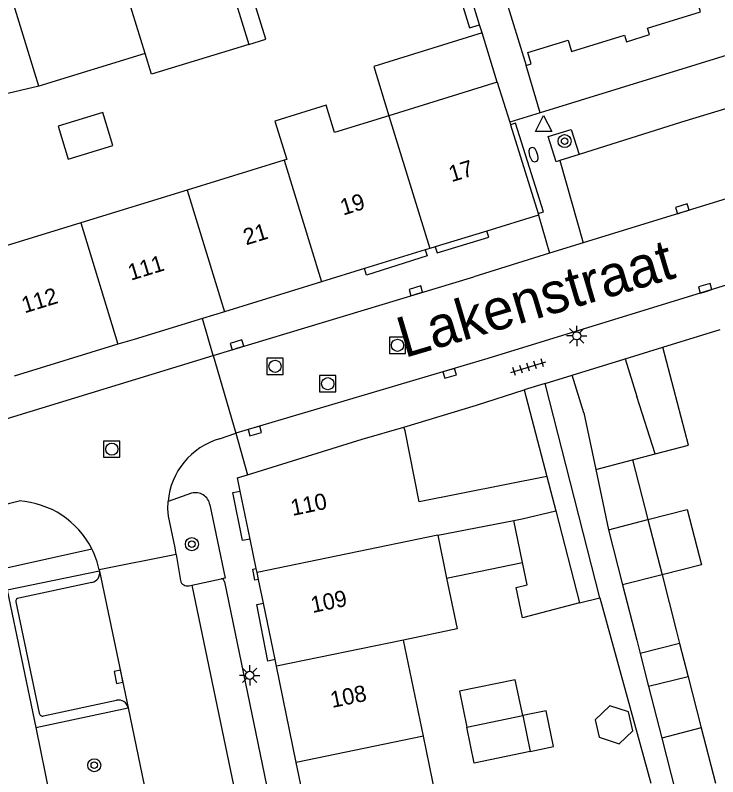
# Model space of a CAD drawing. Extents: x 132999 to 136000, y 398499 to 400501.
# Drawn here: x 133326.11 to 133369.25, y 398548.28 to 398595.04 of the extents above; entities that cross this region are included whole.
import ezdxf

# ---------------------------------------------------------------- set-up
doc = ezdxf.new("R2010")
doc.units = 0
for name, color, linetype in [('gg-afsc-erfafscheiding', 7, 'Continuous'), ('gg-afsc-muur', 7, 'Continuous'), ('gg-anno-huisnummerreeks BGT', 7, 'Continuous'), ('gg-anno-openbare ruimte label', 7, 'Continuous'), ('gg-bbg-bijgebouw', 7, 'Continuous'), ('gg-bbg-gedigitaliseerde bebouwing', 7, 'Continuous'), ('gg-bbg-gedigitaliseerde bijgebouw', 7, 'Continuous'), ('gg-bbg-hoofdgebouw', 7, 'Continuous'), ('gg-bbg-luifel en loopbrug', 7, 'Continuous'), ('gg-bbg-tussenscheiding', 7, 'Continuous'), ('gg-knt-verharding', 7, 'Continuous'), ('gg-knt-verharding nz', 7, 'Continuous'), ('gt-grn-groengrens', 7, 'Continuous'), ('gt-grn-weggrens', 7, 'Continuous'), ('gt-symb-boom', 7, 'Continuous'), ('gt-symb-brandkraan', 7, 'Continuous'), ('gt-symb-kolk', 7, 'Continuous'), ('gt-symb-lichtmast', 7, 'Continuous'), ('gt-symb-rioolschacht', 7, 'Continuous'), ('gt-symb-tegel verharding', 7, 'Continuous'), ('gt-symb-waterafsluiter', 7, 'Continuous')]:
    doc.layers.add(name, color=color, linetype=linetype)

# ---------------------------------------------------------------- blocks, each defined once
blk = doc.blocks.new('gt0-BR')
at = {"layer": 'gt-symb-brandkraan'}
for centre, radius, start, end in [((-0.244, 0), 0.206, 107.5669, 252.4331), ((0.599, -2.664), 3, 106.892, 107.5669), ((0, -0.691), 0.938, 73.108, 106.892), ((-0.599, -2.664), 3, 72.4331, 73.108), ((0.244, 0), 0.206, 287.567, 72.4331), ((0.599, 2.664), 3, 252.4331, 253.108), ((0, 0.691), 0.938, 253.108, 286.8921), ((-0.599, 2.664), 3, 286.8921, 287.567)]:
    blk.add_arc(centre, radius, start, end, dxfattribs=at)
blk = doc.blocks.new('gt0-WAFSL')
at = {"layer": 'gt-symb-waterafsluiter'}
for p, q in [((-0.5, -0.333), (0, 0.667)), ((0, 0.667), (0.5, -0.333)), ((0.5, -0.333), (-0.5, -0.333))]:
    blk.add_line(p, q, dxfattribs=at)
blk = doc.blocks.new('gt0-BOOM')
at = {"layer": 'gt-symb-boom'}
for radius in [0.4, 0.2]:
    blk.add_circle((0, 0), radius, dxfattribs=at)
blk = doc.blocks.new('gt0-KOLK')
at = {"layer": 'gt-symb-kolk'}
blk.add_lwpolyline([(0, 0), (0.375, 0), (0.375, 0.4), (-0.375, 0.4), (-0.375, 0), (0, 0)], dxfattribs=at)
blk = doc.blocks.new('gt0-RS')
at = {"layer": 'gt-symb-rioolschacht'}
blk.add_lwpolyline([(-0.5, -0.5), (0.5, -0.5), (0.5, 0.5), (-0.5, 0.5)], close=True, dxfattribs=at)
blk.add_circle((0, 0), 0.375, dxfattribs=at)
blk = doc.blocks.new('gt0-TEG1')
at = {"layer": 'gt-symb-tegel verharding'}
for p, q in [((-1.125, 0), (1.125, 0)), ((-0.9, -0.25), (-0.9, 0.25)), ((-0.45, -0.25), (-0.45, 0.25)), ((0, -0.25), (0, 0.25)), ((0.45, -0.25), (0.45, 0.25)), ((0.9, -0.25), (0.9, 0.25))]:
    blk.add_line(p, q, dxfattribs=at)
blk = doc.blocks.new('gt0-LMAST')
at = {"layer": 'gt-symb-lichtmast'}
for p, q in [((-0.005, 0.246), (-0.005, 0.621)), ((-0.182, 0.173), (-0.447, 0.438)), ((0.172, 0.173), (0.437, 0.438)), ((-0.255, -0.004), (-0.63, -0.004)), ((-0.182, -0.181), (-0.447, -0.446)), ((-0.005, -0.254), (-0.005, -0.629)), ((0.437, -0.446), (0.172, -0.181)), ((0.245, -0.004), (0.62, -0.004))]:
    blk.add_line(p, q, dxfattribs=at)
blk.add_circle((-0.005, -0.004), 0.25, dxfattribs=at)

msp = doc.modelspace()

# ---------------------------------------------------------------- linework, layer by layer
at = {"layer": 'gg-afsc-erfafscheiding'}
for p, q in [((133358.643, 398572.423), (133360.308, 398572.93)), ((133362.02, 398559.272), (133358.643, 398572.423)), ((133360.77, 398558.953), (133362.02, 398559.272)), ((133362.02, 398559.272), (133365.133, 398547.875))]:
    msp.add_line(p, q, dxfattribs=at)
at = {"layer": 'gg-afsc-muur'}
for p, q in [((133354.783, 398593.959), (133354.63, 398594.458)), ((133365.869, 398574.648), (133369.397, 398575.739)), ((133354.442, 398571.09), (133357.369, 398572.04)), ((133357.369, 398572.04), (133358.753, 398566.716)), ((133349.979, 398569.753), (133354.442, 398571.09))]:
    msp.add_line(p, q, dxfattribs=at)
at = {"layer": 'gg-bbg-bijgebouw'}
for p, q in [((133360.308, 398572.93), (133363.557, 398573.933)), ((133363.557, 398573.933), (133364.29, 398571.627)), ((133361.023, 398570.617), (133360.308, 398572.93)), ((133359.302, 398564.601), (133360.77, 398558.953))]:
    msp.add_line(p, q, dxfattribs=at)
at = {"layer": 'gg-bbg-gedigitaliseerde bebouwing'}
for p, q in [((133355.71, 398590.931), (133349.057, 398588.871)), ((133342.632, 398586.129), (133336.659, 398584.295)), ((133336.659, 398584.295), (133330.128, 398582.29)), ((133330.128, 398582.29), (133323.746, 398580.33)), ((133352.061, 398563.106), (133356.728, 398564.006)), ((133352.061, 398563.106), (133352.603, 398560.479)), ((133351.174, 398550.773), (133349.955, 398556.673)), ((133352.328, 398545.185), (133351.174, 398550.773))]:
    msp.add_line(p, q, dxfattribs=at)
for points in [[(133349.057, 398588.871), (133345.721, 398587.838), (133345.209, 398589.507), (133342.052, 398588.538), (133342.778, 398586.174), (133342.632, 398586.129)], [(133352.603, 398560.479), (133353.247, 398557.353), (133349.955, 398556.673)]]:
    msp.add_lwpolyline(points, dxfattribs=at)
at = {"layer": 'gg-bbg-gedigitaliseerde bijgebouw'}
for p, q in [((133339.589, 398596.039), (133340.446, 398593.25)), ((133334.084, 398592.681), (133327.558, 398590.673)), ((133365.41, 398568.103), (133364.29, 398571.627)), ((133361.023, 398570.617), (133361.757, 398567.143)), ((133364.018, 398567.737), (133365.41, 398568.103)), ((133361.757, 398567.143), (133364.018, 398567.737)), ((133362.538, 398563.443), (133364.96, 398564.064)), ((133364.96, 398564.064), (133365.83, 398560.673)), ((133357.256, 398561.439), (133356.728, 398564.006)), ((133362.538, 398563.443), (133363.407, 398560.053)), ((133365.83, 398560.673), (133366.699, 398557.283)), ((133363.407, 398560.053), (133364.277, 398556.662)), ((133366.699, 398557.283), (133366.908, 398556.468)), ((133364.277, 398556.662), (133364.486, 398555.847)), ((133366.908, 398556.468), (133364.486, 398555.847)), ((133357.272, 398552.032), (133357.727, 398549.828)), ((133368.239, 398551.274), (133365.817, 398550.653)), ((133368.239, 398551.274), (133369.109, 398547.883)), ((133365.817, 398550.653), (133366.687, 398547.262))]:
    msp.add_line(p, q, dxfattribs=at)
for points in [[(133340.446, 398593.25), (133334.472, 398591.416), (133334.084, 398592.681)], [(133327.558, 398590.673), (133322.681, 398589.539), (133322.342, 398591.302), (133320.76, 398591.16)], [(133360.77, 398558.953), (133357.26, 398558.041), (133356.878, 398559.898), (133357.538, 398560.069), (133357.256, 398561.439)], [(133357.272, 398552.032), (133356.818, 398554.235), (133353.39, 398553.528), (133353.845, 398551.324)], [(133361.728, 398551.778), (133361.978, 398550.717), (133363.197, 398550.308), (133364.036, 398551.096), (133363.763, 398552.257), (133362.631, 398552.637), (133361.728, 398551.778)], [(133357.727, 398549.828), (133354.3, 398549.121), (133353.845, 398551.324)]]:
    msp.add_lwpolyline(points, dxfattribs=at)
at = {"layer": 'gg-bbg-hoofdgebouw'}
for p, q in [((133354.47, 398601.751), (133357.49, 398591.961)), ((133355.71, 398590.931), (133356.475, 398588.471)), ((133356.475, 398588.471), (133356.522, 398588.319)), ((133356.522, 398588.319), (133358.22, 398582.856)), ((133358.25, 398582.761), (133355.08, 398581.788)), ((133358.22, 398582.856), (133358.25, 398582.761)), ((133355.08, 398581.788), (133351.901, 398580.812)), ((133351.291, 398580.624), (133347.562, 398579.48)), ((133351.563, 398580.708), (133351.291, 398580.624)), ((133351.901, 398580.812), (133351.563, 398580.708)), ((133347.562, 398579.48), (133344.922, 398578.669)), ((133344.922, 398578.669), (133338.949, 398576.836)), ((133338.949, 398576.836), (133337.614, 398576.426)), ((133337.614, 398576.426), (133333.411, 398575.136)), ((133332.418, 398574.831), (133326.035, 398572.871)), ((133333.411, 398575.136), (133332.418, 398574.831)), ((133339.76, 398566.631), (133340.38, 398566.823)), ((133339.928, 398565.819), (133339.76, 398566.631)), ((133358.753, 398566.716), (133359.302, 398564.601)), ((133340.535, 398562.874), (133339.928, 398565.819)), ((133340.909, 398561.061), (133340.535, 398562.874)), ((133340.96, 398560.816), (133340.909, 398561.061)), ((133341.049, 398560.387), (133340.96, 398560.816)), ((133341.35, 398558.928), (133341.049, 398560.387)), ((133342.063, 398555.473), (133341.35, 398558.928)), ((133342.148, 398555.062), (133342.063, 398555.473)), ((133343.366, 398549.161), (133342.148, 398555.062)), ((133343.71, 398547.495), (133343.366, 398549.161))]:
    msp.add_line(p, q, dxfattribs=at)
for points in [[(133364.938, 398594.247), (133368.2, 398595.251), (133367.98, 398595.941), (133370.45, 398596.711), (133370.67, 398596.021), (133370.815, 398596.063)], [(133363.532, 398593.815), (133363.656, 398593.413), (133365.062, 398593.846), (133364.938, 398594.247)], [(133357.49, 398591.961), (133357.8, 398592.061), (133357.59, 398592.751), (133360.06, 398593.501), (133360.27, 398592.811), (133363.532, 398593.815)], [(133340.38, 398566.823), (133347.424, 398568.998), (133349.979, 398569.753)], [(133358.753, 398566.716), (133350.916, 398565.165), (133350.05, 398569.514), (133349.979, 398569.753)]]:
    msp.add_lwpolyline(points, dxfattribs=at)
at = {"layer": 'gg-bbg-luifel en loopbrug'}
for p, q in [((133354.63, 398594.458), (133353.828, 398597.078)), ((133355.71, 398590.931), (133354.783, 398593.959)), ((133363.557, 398573.933), (133365.869, 398574.648)), ((133364.018, 398567.737), (133364.96, 398564.064)), ((133361.757, 398567.143), (133362.538, 398563.443)), ((133352.603, 398560.479), (133357.256, 398561.439)), ((133366.908, 398556.468), (133367.434, 398554.417)), ((133364.486, 398555.847), (133365.005, 398553.822)), ((133367.434, 398554.417), (133365.005, 398553.822)), ((133367.434, 398554.417), (133368.239, 398551.274)), ((133365.005, 398553.822), (133365.817, 398550.653))]:
    msp.add_line(p, q, dxfattribs=at)
for points in [[(133353.828, 398597.078), (133353.2, 398596.889), (133354.004, 398594.264), (133354.63, 398594.458)], [(133340.446, 398593.25), (133341.488, 398593.57), (133340.631, 398596.36), (133339.589, 398596.039)], [(133354.783, 398593.959), (133348.128, 398591.899), (133349.057, 398588.871)], [(133329.361, 398586.196), (133332.108, 398587.039), (133331.486, 398589.068), (133328.738, 398588.224), (133329.361, 398586.196)], [(133365.41, 398568.103), (133367.448, 398568.639), (133365.869, 398574.648)], [(133364.96, 398564.064), (133367.383, 398564.685), (133368.253, 398561.293), (133365.83, 398560.673)], [(133357.727, 398549.828), (133359.167, 398550.125), (133358.712, 398552.329), (133357.272, 398552.032)]]:
    msp.add_lwpolyline(points, dxfattribs=at)
at = {"layer": 'gg-bbg-tussenscheiding'}
for p, q in [((133334.084, 398592.681), (133332.549, 398597.68)), ((133327.558, 398590.673), (133326.02, 398595.671)), ((133349.057, 398588.871), (133351.563, 398580.708)), ((133342.632, 398586.129), (133344.922, 398578.669)), ((133336.659, 398584.295), (133338.949, 398576.836)), ((133330.128, 398582.29), (133332.418, 398574.831)), ((133352.061, 398563.106), (133340.96, 398560.816)), ((133365.83, 398560.673), (133363.407, 398560.053)), ((133349.955, 398556.673), (133342.148, 398555.062)), ((133353.845, 398551.324), (133357.272, 398552.032)), ((133351.174, 398550.773), (133343.366, 398549.161))]:
    msp.add_line(p, q, dxfattribs=at)
msp.add_lwpolyline([(133356.728, 398564.006), (133357.248, 398564.106), (133359.302, 398564.601)], dxfattribs=at)
at = {"layer": 'gg-knt-verharding'}
for p, q in [((133385.03, 398597.285), (133358.34, 398589.051)), ((133358.34, 398589.051), (133357.49, 398591.961)), ((133360.738, 398586.493), (133359.551, 398586.12)), ((133359.551, 398586.12), (133360.979, 398581.06)), ((133360.979, 398581.06), (133358.911, 398580.42)), ((133358.911, 398580.42), (133354.27, 398578.985)), ((133376.732, 398580.602), (133355.131, 398573.956)), ((133338.269, 398574.153), (133354.27, 398578.985)), ((133322.345, 398569.283), (133338.269, 398574.153)), ((133338.269, 398574.153), (133339.645, 398569.375)), ((133355.131, 398573.956), (133339.645, 398569.375)), ((133338.654, 398569.021), (133339.645, 398569.375)), ((133336.934, 398565.681), (133335.497, 398565.184)), ((133335.986, 398561.923), (133331.269, 398560.98)), ((133335.986, 398561.923), (133336.25, 398560.326)), ((133331.269, 398560.98), (133331.286, 398560.901)), ((133336.955, 398560.038), (133338.762, 398560.429)), ((133330.82, 398560.208), (133326.328, 398559.245)), ((133336.785, 398560.001), (133336.955, 398560.038)), ((133338.96, 398560.244), (133348.505, 398514.204)), ((133326.149, 398559.022), (133327.585, 398552.179)), ((133327.84, 398552.011), (133332.324, 398552.979)), ((133327.363, 398551.302), (133333.051, 398552.517)), ((133333.051, 398552.517), (133334.344, 398546.217))]:
    msp.add_line(p, q, dxfattribs=at)
for points in [[(133371.968, 398589.96), (133367.027, 398588.469), (133360.738, 398586.493)], [(133358.22, 398582.856), (133358.555, 398582.96), (133356.837, 398588.417), (133356.522, 398588.319)], [(133359.551, 398586.12), (133359.319, 398586.047), (133358.83, 398587.602), (133360.258, 398588.02), (133360.738, 398586.493)], [(133351.901, 398580.812), (133352.015, 398580.44), (133355.193, 398581.418), (133355.08, 398581.788)], [(133351.291, 398580.624), (133351.402, 398580.261), (133347.686, 398579.078), (133347.562, 398579.48)], [(133340.535, 398562.874), (133340.071, 398562.778), (133339.466, 398565.723), (133339.928, 398565.819)], [(133323.859, 398564.499), (133325.785, 398565.078), (133326.346, 398565.212)], [(133335.986, 398561.923), (133335.92, 398562.325), (133335.517, 398564.286), (133335.484, 398564.735), (133335.497, 398565.184)], [(133338.06, 398564.983), (133338.994, 398560.479), (133338.762, 398560.429)], [(133333.628, 398510.589), (133322.789, 398560.498), (133330.81, 398562.273)], [(133331.286, 398560.901), (133325.611, 398559.727), (133327.363, 398551.302)], [(133341.049, 398560.387), (133340.826, 398560.341), (133340.697, 398561.018), (133340.909, 398561.061)], [(133342.063, 398555.473), (133341.628, 398555.383), (133340.955, 398558.847), (133341.35, 398558.928)]]:
    msp.add_lwpolyline(points, dxfattribs=at)
for centre, radius, start, end in [((133339.841, 398564.827), 4.359, 105.8021, 175.3043), ((133337.184, 398564.827), 0.89, 10.0994, 106.3116), ((133326.011, 398559.843), 5.379, 26.8531, 86.4269), ((133325.864, 398559.789), 5.534, 12.4239, 26.6647), ((133330.697, 398560.794), 0.598, 281.8318, 10.3313), ((133336.69, 398560.448), 0.457, 195.5003, 281.9443), ((133338.777, 398560.246), 0.183, 359.3309, 94.5572), ((133326.335, 398559.056), 0.189, 92.1116, 190.381), ((133332.44, 398552.358), 0.632, 14.5903, 100.5387), ((133327.777, 398552.193), 0.193, 184.1869, 289.0574)]:
    msp.add_arc(centre, radius, start, end, dxfattribs=at)
at = {"layer": 'gg-knt-verharding nz'}
for p, q in [((133387.342, 398589.212), (133360.979, 398581.06)), ((133331.286, 398560.901), (133333.051, 398552.517)), ((133336.955, 398560.038), (133346.599, 398513.58))]:
    msp.add_line(p, q, dxfattribs=at)
at = {"layer": 'gt-grn-groengrens'}
msp.add_line((133327.363, 398551.302), (133328.647, 398545.052), dxfattribs=at)
at = {"layer": 'gt-grn-weggrens'}
for p, q in [((133358.34, 398589.051), (133356.475, 398588.471)), ((133358.25, 398582.761), (133358.911, 398580.42)), ((133338.269, 398574.153), (133337.614, 398576.426)), ((133358.643, 398572.423), (133357.369, 398572.04)), ((133339.645, 398569.375), (133340.38, 398566.823))]:
    msp.add_line(p, q, dxfattribs=at)

# ---------------------------------------------------------------- block references
at = {"layer": 'gt-symb-boom'}
for p in [(133359.85, 398587.307), (133336.954, 398562.56), (133330.962, 398548.984)]:
    msp.add_blockref('gt0-BOOM', p, dxfattribs=at)
at = {"layer": 'gt-symb-brandkraan', "rotation": 107.27542027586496}
msp.add_blockref('gt0-BR', (133357.935, 398586.477), dxfattribs=at)
at = {"layer": 'gt-symb-kolk'}
for p, rotation in [((133367.132, 398582.963), 17.16594606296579), ((133368.54, 398578.081), 17.094305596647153), ((133350.767, 398577.927), 16.79895483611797), ((133339.781, 398574.61), 16.798954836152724), ((133352.729, 398573.244), -163.48704137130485), ((133340.766, 398569.703), -163.71429420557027), ((133332.644, 398554.45), 101.89073602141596)]:
    msp.add_blockref('gt0-KOLK', p, dxfattribs=dict(at, rotation=rotation))
at = {"layer": 'gt-symb-lichtmast'}
for p in [(133360.598, 398575.355), (133340.511, 398554.507)]:
    msp.add_blockref('gt0-LMAST', p, dxfattribs=at)
at = {"layer": 'gt-symb-rioolschacht'}
for p in [(133349.585, 398574.771), (133342.063, 398573.481), (133345.298, 398572.413), (133332.038, 398568.393)]:
    msp.add_blockref('gt0-RS', p, dxfattribs=at)
at = {"layer": 'gt-symb-tegel verharding', "rotation": 17.09430559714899}
msp.add_blockref('gt0-TEG1', (133357.61, 398573.427), dxfattribs=at)
at = {"layer": 'gt-symb-waterafsluiter'}
msp.add_blockref('gt0-WAFSL', (133358.555, 398588.225), dxfattribs=at)

# ---------------------------------------------------------------- texts
at = {"layer": 'gg-anno-huisnummerreeks BGT'}
for s, rotation, p in [('17', 17, (133352.907, 398584.783)), ('19', 17.1, (133346.247, 398582.737)), ('21', 17, (133340.286, 398580.908)), ('111', 17, (133333.206, 398578.735)), ('112', 17.1, (133326.677, 398576.728)), ('110', 11.7, (133343.137, 398564.291)), ('109', 11.7, (133344.368, 398558.329)), ('108', 11.7, (133345.571, 398552.5))]:
    msp.add_text(s, height=1, rotation=rotation, dxfattribs=at).set_placement(p)
at = {"layer": 'gg-anno-openbare ruimte label'}
msp.add_text('Lakenstraat', height=2.5, rotation=16.5, dxfattribs=at).set_placement((133350.017, 398573.982))

doc.saveas('drawing.dxf')
